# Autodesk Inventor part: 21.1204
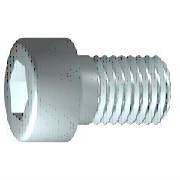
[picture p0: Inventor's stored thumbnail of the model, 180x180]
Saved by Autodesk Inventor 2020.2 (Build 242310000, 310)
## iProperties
Created: 2006-02
Part Number: 21.1204
Material: Steel, Mild
Description: M8 x 25 SHCS
Document SubType Name: Modeling
Standard: DIN 7984
Designer: Andy Moles
Standards Organization: DIN
Language: en-US
Size Designation: M8 x 25
Categories: <MemberInstance><Categories><Category DisplayName="Fasteners" InternalName="e4da775c-781d-43d5-af7c-5136215cf5a6" Mnemonic="FSTN"><Category DisplayName="Bolts"
Density: 7.85 g/cm^3
Mass: 14.2203 g
Surface Area: 11.4333 cm^2
Volume: 1.81151 cm^3
Vendor: S
Appearance: Zinc
Author: Andy Moles
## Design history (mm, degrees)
sketch "Sketch1"
  geometry: L1 (0.467, 0)-(25, 0); L2 (25, 0)-(25, 4); L3 (25, 4)-(1, 4); L4 (1, 4)-(0.233, 4); L5 (0.233, 4)-(0, 4); L6 (0, 4)-(0, 6.5); L7 (0, 6.5)-(-5, 6.5); L8 (-5, 6.5)-(-5, 2.887); L9 (-5, 2.887)-(-1.2, 2.887); L10 (-1.2, 2.887)-(0.467, 0); L11 (-8, 0)-(34, 0) reference; L12 (0, -0.65)-(0, 8.45) reference; L13 (1, 4)-(0, 4)
  constraints: 22 end point, 6 parallel, 2 collinear, 2 perpendicular, 1 horizontal, 1 point on line
  dimensions: "d1" = 24 distance from line of L3.end L2 (= GEL); "d2" = 0.76691 distance of L4.end L3.end (computed from GAL); "d3" = 5 distance between parallel lines of L8 L6 (= KOH); "d4" = 3.8 distance of L8.end L9.end (= INTI); "d5" = 60 deg angle of L10 L1; "d6" = 8 diameter of L3 L1 (= GD); "d7" = 8 diameter of L5 L1 (= BDM); "d8" = 5.7735 diameter of L9 L1 (= 1.1547 x SW); "d9" = 13 diameter of L7 L1 (= KOD); "d26" = 25 distance between parallel lines of L12 L2 (= NLG)
revolve "Body" sketch "Sketch1" stored, may be unused: angle "d10" = 90 deg
sketch "Sketch2"
  geometry: L1 (0, -7.8)-(0, 10.4) reference; L2 (-7.8, 0)-(10.4, 0) reference; L3 (2.887, 0)-(1.443, -2.5); L4 (1.443, -2.5)-(-1.443, -2.5); L5 (-1.443, -2.5)-(-2.887, 0); L6 (-2.887, 0)-(-1.443, 2.5); L7 (-1.443, 2.5)-(1.443, 2.5); L8 (1.443, 2.5)-(2.887, 0); 2 further points
  constraints: 12 end point, 1 coincident, 1 horizontal alignment, 1 point on line, 12 other
extrude "Slot" join sketch "Sketch2" stored distance "d11" = 10; taper "d12" = 0 deg
workplane "Work Plane1"
body "Solid1"
fillet "Fillet1" dims "d17" = 0.8 (= RR)
feature "Thread" dims "d13" = 25, "d14" = 0
chamfer "Chamfer1" distance "d15" = 0.76681 (= -0.5 x SPD + 0.5 x GD); stored, may be unused: second distance "d16" = 0.76681 (= GUL), angle "d27" = 45 deg
other parameters: "GD" = 8 (= NND) [user parameter; used in 2 equation terms], "NLG" = 25 [user parameter; used in 1 equation term], "GEL" = 24 [user parameter; used in 1 equation term], "KOD" = 13 [user parameter; used in 1 equation term], "KOH" = 5 [user parameter; used in 1 equation term], "INTI" = 3.8 [user parameter; used in 1 equation term], "GAL" = 0.76681 (= 0.61345 x PTC) [user parameter; used in 1 equation term], "GUL" = 0.76681 (= 0.61345 x PTC) [user parameter; used in 1 equation term], "BDM" = 8 (= NND) [user parameter; used in 1 equation term], "SW" = 5 [user parameter; used in 2 equation terms], "RR" = 0.8 [user parameter; used in 1 equation term], "SPD" = 6.46637 (= NND - 1.2269 x PTC) [user parameter; used in 1 equation term], "d19" = 0, "d28" = 0, "d29" = 0, "TOA" = 30 deg [user parameter], "GD1" = 6.46637 (= THREADDIA - 1.2269 x PTC) [user parameter], "THREADDIA" = 8 [user parameter; used in 1 equation term], "FAWI" = 45 deg [user parameter], "ANG" = 120 deg [user parameter], "TPU" = 8 (computed from PTC) [user parameter], "PTC" = 1.25 [user parameter; used in 5 equation terms], "NND" = 8 [user parameter; used in 3 equation terms], "E0" = 5.775 (= 1.155 x SW) [user parameter]
